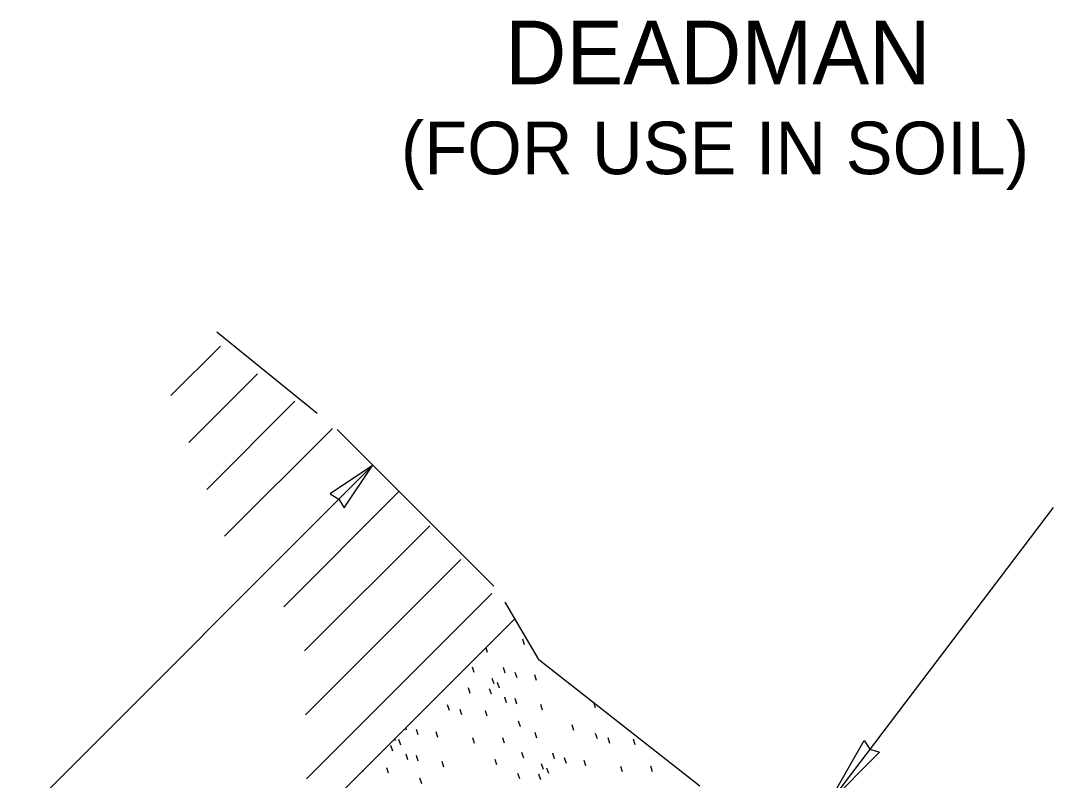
# Model space of a CAD drawing. Extents: x 99861 to 103151, y 100000 to 102076.
# Drawn here: x 100259.6 to 100583.5, y 100519.2 to 100757.9 of the extents above; entities that cross this region are included whole.
import ezdxf

# ---------------------------------------------------------------- set-up
doc = ezdxf.new("R2010")
doc.units = 0
for name, color, linetype in [('Level 10', 7, 'Continuous'), ('Level 15', 7, 'Continuous'), ('Level 18', 7, 'Continuous'), ('Level 2', 7, 'Continuous'), ('Level 8', 7, 'Continuous')]:
    doc.layers.add(name, color=color, linetype=linetype)

msp = doc.modelspace()

# ---------------------------------------------------------------- linework, layer by layer
at = {"layer": 'Level 10'}
for p, q in [((100306.85, 100640.13), (100322.41, 100655.69)), ((100312.47, 100625.39), (100334.03, 100646.94)), ((100318.1, 100610.65), (100345.8, 100638.36)), ((100318.1, 100610.65), (100345.8, 100638.36)), ((100323.72, 100595.91), (100357.58, 100629.77)), ((100342.3, 100573.76), (100378.39, 100609.85)), ((100342.3, 100573.76), (100378.39, 100609.85)), ((100348.82, 100559.91), (100388.14, 100599.23)), ((100349.11, 100539.84), (100397.89, 100588.61)), ((100349.41, 100519.77), (100407.63, 100578)), ((100349.41, 100519.77), (100407.63, 100578))]:
    msp.add_line(p, q, dxfattribs=at)
at = {"layer": 'Level 15'}
for p, q in [((100359.02, 100629.51), (100408.27, 100580.3)), ((100370.21, 100618.21), (100044.49, 100292.32)), ((100584, 100605), (100512.76, 100511.1))]:
    msp.add_line(p, q, dxfattribs=at)
for points in [[(100370.21, 100618.21), (100356.92, 100609.27), (100359.61, 100607.6), (100361.28, 100604.91)], [(100513.24, 100511.74), (100524.66, 100531.73), (100526.4, 100529.08), (100529.42, 100528.12)]]:
    msp.add_lwpolyline(points, close=True, dxfattribs=at)
at = {"layer": 'Level 2'}
for points in [[(100352.82, 100634.53), (100321.27, 100660.03)], [(100422.41, 100557.25), (100411.86, 100575.18)], [(100240.46, 100395.54), (100414.92, 100569.98)], [(100422.41, 100557.25), (100473.01, 100517.51)]]:
    msp.add_lwpolyline(points, dxfattribs=at)
at = {"layer": 'Level 8'}
for p, q in [((100417.94, 100561.82), (100417.37, 100563.57)), ((100406.33, 100559.37), (100405.83, 100560.89)), ((100402.16, 100553.09), (100401.59, 100554.84)), ((100411.87, 100552.9), (100411.3, 100554.65)), ((100415.57, 100551.41), (100415, 100553.15)), ((100408.38, 100549.53), (100407.81, 100551.27)), ((100410.05, 100548.22), (100409.48, 100549.97)), ((100421.7, 100550.62), (100421.13, 100552.37)), ((100400.9, 100546.56), (100400.33, 100548.31)), ((100407.53, 100546.31), (100406.96, 100548.05)), ((100412.27, 100543.63), (100411.7, 100545.37)), ((100415.54, 100543.2), (100414.97, 100544.94)), ((100440.23, 100541.98), (100439.67, 100543.69)), ((100394.32, 100541.22), (100393.75, 100542.96)), ((100398.24, 100539.78), (100397.67, 100541.53)), ((100406.22, 100539.36), (100405.65, 100541.11)), ((100423.61, 100541.28), (100423.04, 100543.03)), ((100416.62, 100536.08), (100416.05, 100537.83)), ((100433.45, 100534.96), (100432.88, 100536.71)), ((100447.4, 100537.6), (100447.39, 100537.62)), ((100380.88, 100535.01), (100380.65, 100535.71)), ((100384.57, 100533.51), (100384, 100535.26)), ((100390.71, 100532.73), (100390.14, 100534.47)), ((100421.83, 100532.51), (100421.26, 100534.26)), ((100440.82, 100532.25), (100440.25, 100534)), ((100377.38, 100531.63), (100377.18, 100532.25)), ((100379.06, 100530.33), (100378.49, 100532.07)), ((100402.23, 100530.87), (100401.66, 100532.61)), ((100411.68, 100530.91), (100411.11, 100532.65)), ((100444.74, 100530.82), (100444.17, 100532.57)), ((100452.72, 100530.4), (100452.15, 100532.15)), ((100376.53, 100528.41), (100375.96, 100530.16)), ((100381.27, 100525.73), (100380.7, 100527.48)), ((100384.55, 100525.3), (100383.98, 100527.05)), ((100417.67, 100526.24), (100417.09, 100527.98)), ((100427.38, 100526.04), (100426.81, 100527.79)), ((100392.62, 100523.38), (100392.05, 100525.13)), ((100409.24, 100524.08), (100408.67, 100525.83)), ((100423.88, 100522.67), (100423.31, 100524.42)), ((100431.07, 100524.55), (100430.5, 100526.3)), ((100437.21, 100523.76), (100436.64, 100525.51)), ((100367.24, 100521.89), (100367.14, 100522.21)), ((100375.22, 100521.47), (100374.65, 100523.21)), ((100416.41, 100519.71), (100415.83, 100521.45)), ((100423.03, 100519.45), (100422.46, 100521.2)), ((100425.56, 100521.37), (100424.99, 100523.11)), ((100448.73, 100521.9), (100448.16, 100523.65)), ((100458.18, 100521.95), (100457.61, 100523.69)), ((100385.63, 100518.19), (100385.06, 100519.93))]:
    msp.add_line(p, q, dxfattribs=at)

# ---------------------------------------------------------------- texts
at = {"layer": 'Level 18'}
for s, height, p in [('DEADMAN', 20, (100411.77, 100737.93)), ('(FOR USE IN SOIL)', 16.5, (100379.09, 100709.68))]:
    msp.add_text(s, height=height, dxfattribs=at).set_placement(p)

doc.saveas('drawing.dxf')
